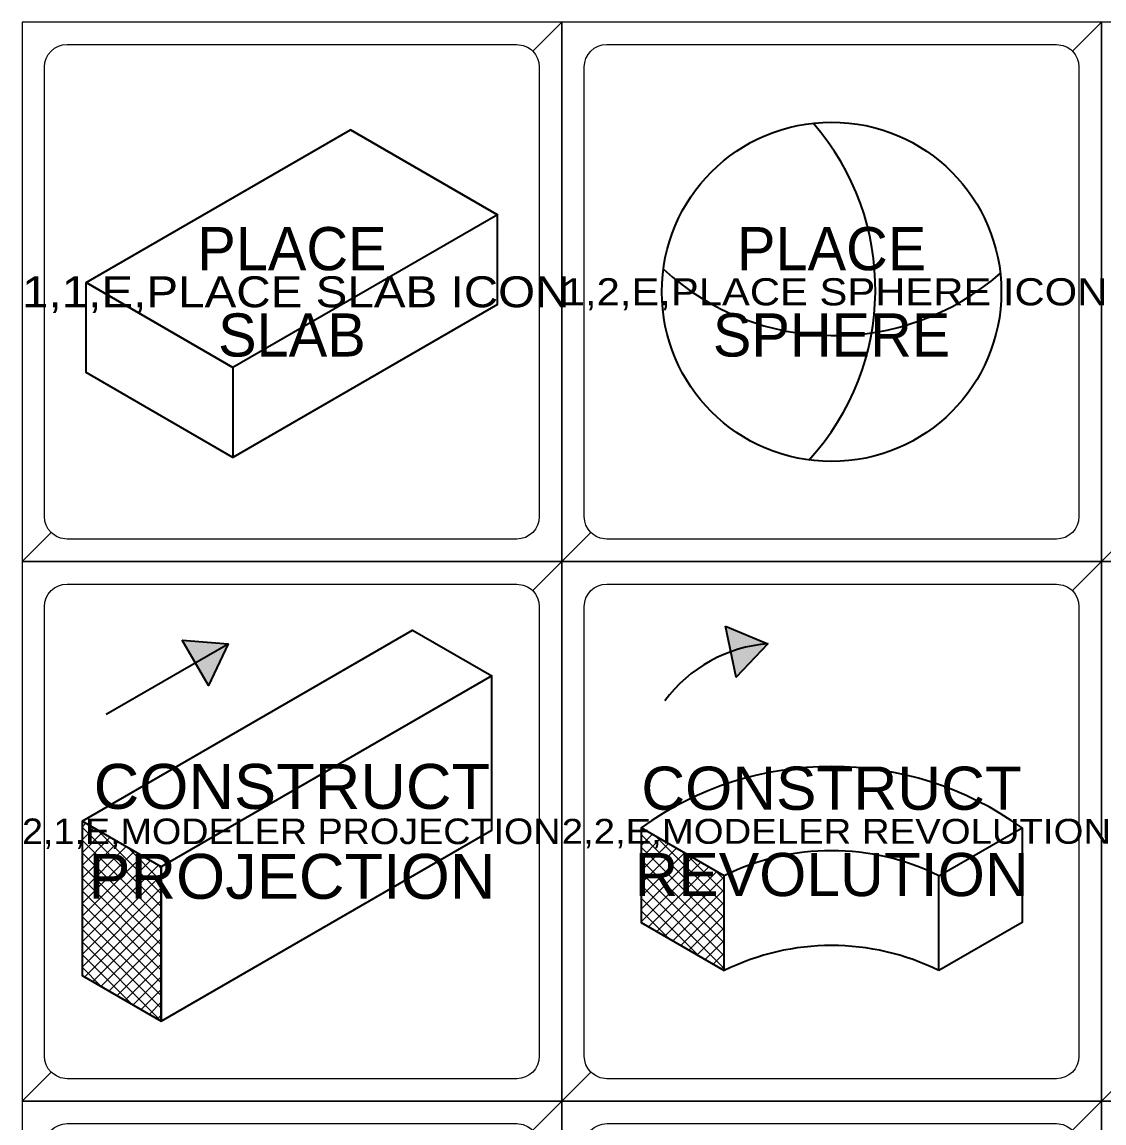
# Model space of a CAD drawing. Extents: x 95909.2 to 95923.3, y 90965 to 90971.2.
# Drawn here: x 95909.787 to 95910.99, y 90969.936 to 90971.16 of the extents above; entities that cross this region are included whole.
import ezdxf
from ezdxf.enums import TextEntityAlignment as Align

# ---------------------------------------------------------------- set-up
doc = ezdxf.new("R2010")
doc.units = 0
doc.header["$LTSCALE"] = 0.019
for name, color, linetype, lineweight in [('1', 7, 'Continuous', 25), ('10', 7, 'Continuous', 13), ('2', 7, 'Continuous', 25), ('3', 7, 'Continuous', 25), ('4', 7, 'Continuous', 25), ('6', 7, 'Continuous', 13)]:
    doc.layers.add(name, color=color, linetype=linetype, lineweight=lineweight)
doc.layers.add('5', color=7, linetype='Continuous')
doc.layers.add('63', color=7, linetype='Continuous')

msp = doc.modelspace()

# ---------------------------------------------------------------- hatches: boundary and pattern name
at = {"layer": '6'}
for points in [[(95910.5687, 90970.4886), (95910.6161, 90970.469), (95910.5807, 90970.4316)], [(95909.9649, 90970.473), (95910.0161, 90970.469), (95909.9941, 90970.4226)]]:
    msp.add_hatch(color=256, dxfattribs=at).paths.add_polyline_path(points)

# ---------------------------------------------------------------- linework, layer by layer
at = {"layer": '1'}
for points in [[(95909.7868, 90970.5603), (95910.3868, 90970.5603), (95910.3868, 90971.1603), (95909.7868, 90971.1603)], [(95910.3868, 90970.5603), (95910.9868, 90970.5603), (95910.9868, 90971.1603), (95910.3868, 90971.1603)], [(95910.9868, 90970.5603), (95911.5868, 90970.5603), (95911.5868, 90971.1603), (95910.9868, 90971.1603)], [(95909.7868, 90969.9603), (95910.3868, 90969.9603), (95910.3868, 90970.5603), (95909.7868, 90970.5603)], [(95910.3868, 90969.9603), (95910.9868, 90969.9603), (95910.9868, 90970.5603), (95910.3868, 90970.5603)], [(95910.9868, 90969.9603), (95911.5868, 90969.9603), (95911.5868, 90970.5603), (95910.9868, 90970.5603)], [(95909.7868, 90969.3603), (95910.3868, 90969.3603), (95910.3868, 90969.9603), (95909.7868, 90969.9603)], [(95910.3868, 90969.3603), (95910.9868, 90969.3603), (95910.9868, 90969.9603), (95910.3868, 90969.9603)], [(95910.9868, 90969.3603), (95911.5868, 90969.3603), (95911.5868, 90969.9603), (95910.9868, 90969.9603)]]:
    msp.add_lwpolyline(points, close=True, dxfattribs=at)
at = {"layer": '10'}
msp.add_lwpolyline([(95909.7868, 90971.1603), (95915.7868, 90971.1603), (95915.7868, 90966.3603), (95909.7868, 90966.3603)], close=True, dxfattribs=at)
at = {"layer": '2'}
for points in [[(95909.7868, 90970.5603), (95910.3868, 90970.5603), (95910.3868, 90971.1603), (95909.7868, 90971.1603)], [(95910.3868, 90970.5603), (95910.9868, 90970.5603), (95910.9868, 90971.1603), (95910.3868, 90971.1603)], [(95910.9868, 90970.5603), (95911.5868, 90970.5603), (95911.5868, 90971.1603), (95910.9868, 90971.1603)], [(95909.7868, 90969.9603), (95910.3868, 90969.9603), (95910.3868, 90970.5603), (95909.7868, 90970.5603)], [(95910.3868, 90969.9603), (95910.9868, 90969.9603), (95910.9868, 90970.5603), (95910.3868, 90970.5603)], [(95910.9868, 90969.9603), (95911.5868, 90969.9603), (95911.5868, 90970.5603), (95910.9868, 90970.5603)], [(95909.7868, 90969.3603), (95910.3868, 90969.3603), (95910.3868, 90969.9603), (95909.7868, 90969.9603)], [(95910.3868, 90969.3603), (95910.9868, 90969.3603), (95910.9868, 90969.9603), (95910.3868, 90969.9603)], [(95910.9868, 90969.3603), (95911.5868, 90969.3603), (95911.5868, 90969.9603), (95910.9868, 90969.9603)]]:
    msp.add_lwpolyline(points, close=True, dxfattribs=at)
at = {"layer": '3'}
for points in [[(95910.3868, 90971.1603), (95909.7868, 90971.1603), (95909.7868, 90970.5603), (95909.8191, 90970.5926), (95909.816, 90970.5964), (95909.8137, 90970.6007), (95909.8123, 90970.6054), (95909.8118, 90970.6103), (95909.8118, 90971.1103), (95909.8123, 90971.1152), (95909.8137, 90971.1199), (95909.816, 90971.1242), (95909.8191, 90971.128), (95909.8191, 90971.128), (95909.8229, 90971.1311), (95909.8272, 90971.1334), (95909.8319, 90971.1348), (95909.8368, 90971.1353), (95910.3368, 90971.1353), (95910.3441, 90971.1342), (95910.3486, 90971.1323), (95910.3527, 90971.1296), (95910.3545, 90971.128)], [(95910.9868, 90971.1603), (95910.3868, 90971.1603), (95910.3868, 90970.5603), (95910.4191, 90970.5926), (95910.416, 90970.5964), (95910.4137, 90970.6007), (95910.4123, 90970.6054), (95910.4118, 90970.6103), (95910.4118, 90971.1103), (95910.4123, 90971.1152), (95910.4137, 90971.1199), (95910.416, 90971.1242), (95910.4191, 90971.128), (95910.4191, 90971.128), (95910.4229, 90971.1311), (95910.4272, 90971.1334), (95910.4319, 90971.1348), (95910.4368, 90971.1353), (95910.9368, 90971.1353), (95910.9441, 90971.1342), (95910.9486, 90971.1323), (95910.9527, 90971.1296), (95910.9545, 90971.128)], [(95911.5868, 90971.1603), (95910.9868, 90971.1603), (95910.9868, 90970.5603), (95911.0191, 90970.5926), (95911.016, 90970.5964), (95911.0137, 90970.6007), (95911.0123, 90970.6054), (95911.0118, 90970.6103), (95911.0118, 90971.1103), (95911.0123, 90971.1152), (95911.0137, 90971.1199), (95911.016, 90971.1242), (95911.0191, 90971.128), (95911.0191, 90971.128), (95911.0229, 90971.1311), (95911.0272, 90971.1334), (95911.0319, 90971.1348), (95911.0368, 90971.1353), (95911.5368, 90971.1353), (95911.5441, 90971.1342), (95911.5486, 90971.1323), (95911.5527, 90971.1296), (95911.5545, 90971.128)], [(95910.3868, 90970.5603), (95909.7868, 90970.5603), (95909.7868, 90969.9603), (95909.8191, 90969.9926), (95909.816, 90969.9964), (95909.8137, 90970.0007), (95909.8123, 90970.0054), (95909.8118, 90970.0103), (95909.8118, 90970.5103), (95909.8123, 90970.5152), (95909.8137, 90970.5199), (95909.816, 90970.5242), (95909.8191, 90970.528), (95909.8191, 90970.528), (95909.8229, 90970.5311), (95909.8272, 90970.5334), (95909.8319, 90970.5348), (95909.8368, 90970.5353), (95910.3368, 90970.5353), (95910.3441, 90970.5342), (95910.3486, 90970.5323), (95910.3527, 90970.5296), (95910.3545, 90970.528)], [(95910.9868, 90970.5603), (95910.3868, 90970.5603), (95910.3868, 90969.9603), (95910.4191, 90969.9926), (95910.416, 90969.9964), (95910.4137, 90970.0007), (95910.4123, 90970.0054), (95910.4118, 90970.0103), (95910.4118, 90970.5103), (95910.4123, 90970.5152), (95910.4137, 90970.5199), (95910.416, 90970.5242), (95910.4191, 90970.528), (95910.4191, 90970.528), (95910.4229, 90970.5311), (95910.4272, 90970.5334), (95910.4319, 90970.5348), (95910.4368, 90970.5353), (95910.9368, 90970.5353), (95910.9441, 90970.5342), (95910.9486, 90970.5323), (95910.9527, 90970.5296), (95910.9545, 90970.528)], [(95911.5868, 90970.5603), (95910.9868, 90970.5603), (95910.9868, 90969.9603), (95911.0191, 90969.9926), (95911.016, 90969.9964), (95911.0137, 90970.0007), (95911.0123, 90970.0054), (95911.0118, 90970.0103), (95911.0118, 90970.5103), (95911.0123, 90970.5152), (95911.0137, 90970.5199), (95911.016, 90970.5242), (95911.0191, 90970.528), (95911.0191, 90970.528), (95911.0229, 90970.5311), (95911.0272, 90970.5334), (95911.0319, 90970.5348), (95911.0368, 90970.5353), (95911.5368, 90970.5353), (95911.5441, 90970.5342), (95911.5486, 90970.5323), (95911.5527, 90970.5296), (95911.5545, 90970.528)], [(95910.3868, 90969.9603), (95909.7868, 90969.9603), (95909.7868, 90969.3603), (95909.8191, 90969.3926), (95909.816, 90969.3964), (95909.8137, 90969.4007), (95909.8123, 90969.4054), (95909.8118, 90969.4103), (95909.8118, 90969.9103), (95909.8123, 90969.9152), (95909.8137, 90969.9199), (95909.816, 90969.9242), (95909.8191, 90969.928), (95909.8191, 90969.928), (95909.8229, 90969.9311), (95909.8272, 90969.9334), (95909.8319, 90969.9348), (95909.8368, 90969.9353), (95910.3368, 90969.9353), (95910.3441, 90969.9342), (95910.3486, 90969.9323), (95910.3527, 90969.9296), (95910.3545, 90969.928)], [(95910.9868, 90969.9603), (95910.3868, 90969.9603), (95910.3868, 90969.3603), (95910.4191, 90969.3926), (95910.416, 90969.3964), (95910.4137, 90969.4007), (95910.4123, 90969.4054), (95910.4118, 90969.4103), (95910.4118, 90969.9103), (95910.4123, 90969.9152), (95910.4137, 90969.9199), (95910.416, 90969.9242), (95910.4191, 90969.928), (95910.4191, 90969.928), (95910.4229, 90969.9311), (95910.4272, 90969.9334), (95910.4319, 90969.9348), (95910.4368, 90969.9353), (95910.9368, 90969.9353), (95910.9441, 90969.9342), (95910.9486, 90969.9323), (95910.9527, 90969.9296), (95910.9545, 90969.928)], [(95911.5868, 90969.9603), (95910.9868, 90969.9603), (95910.9868, 90969.3603), (95911.0191, 90969.3926), (95911.016, 90969.3964), (95911.0137, 90969.4007), (95911.0123, 90969.4054), (95911.0118, 90969.4103), (95911.0118, 90969.9103), (95911.0123, 90969.9152), (95911.0137, 90969.9199), (95911.016, 90969.9242), (95911.0191, 90969.928), (95911.0191, 90969.928), (95911.0229, 90969.9311), (95911.0272, 90969.9334), (95911.0319, 90969.9348), (95911.0368, 90969.9353), (95911.5368, 90969.9353), (95911.5441, 90969.9342), (95911.5486, 90969.9323), (95911.5527, 90969.9296), (95911.5545, 90969.928)]]:
    msp.add_lwpolyline(points, close=True, dxfattribs=at)
at = {"layer": '4'}
for points in [[(95909.7868, 90970.5603), (95910.3868, 90970.5603), (95910.3868, 90971.1603), (95910.3545, 90971.128), (95910.3576, 90971.1242), (95910.3599, 90971.1199), (95910.3613, 90971.1152), (95910.3618, 90971.1103), (95910.3618, 90970.6103), (95910.3613, 90970.6054), (95910.3599, 90970.6007), (95910.3576, 90970.5964), (95910.3545, 90970.5926), (95910.3545, 90970.5926), (95910.3507, 90970.5895), (95910.3464, 90970.5872), (95910.3417, 90970.5858), (95910.3368, 90970.5853), (95909.8368, 90970.5853), (95909.8295, 90970.5864), (95909.825, 90970.5883), (95909.8209, 90970.591), (95909.8191, 90970.5926)], [(95910.3868, 90970.5603), (95910.9868, 90970.5603), (95910.9868, 90971.1603), (95910.9545, 90971.128), (95910.9576, 90971.1242), (95910.9599, 90971.1199), (95910.9613, 90971.1152), (95910.9618, 90971.1103), (95910.9618, 90970.6103), (95910.9613, 90970.6054), (95910.9599, 90970.6007), (95910.9576, 90970.5964), (95910.9545, 90970.5926), (95910.9545, 90970.5926), (95910.9507, 90970.5895), (95910.9464, 90970.5872), (95910.9417, 90970.5858), (95910.9368, 90970.5853), (95910.4368, 90970.5853), (95910.4295, 90970.5864), (95910.425, 90970.5883), (95910.4209, 90970.591), (95910.4191, 90970.5926)], [(95910.9868, 90970.5603), (95911.5868, 90970.5603), (95911.5868, 90971.1603), (95911.5545, 90971.128), (95911.5576, 90971.1242), (95911.5599, 90971.1199), (95911.5613, 90971.1152), (95911.5618, 90971.1103), (95911.5618, 90970.6103), (95911.5613, 90970.6054), (95911.5599, 90970.6007), (95911.5576, 90970.5964), (95911.5545, 90970.5926), (95911.5545, 90970.5926), (95911.5507, 90970.5895), (95911.5464, 90970.5872), (95911.5417, 90970.5858), (95911.5368, 90970.5853), (95911.0368, 90970.5853), (95911.0295, 90970.5864), (95911.025, 90970.5883), (95911.0209, 90970.591), (95911.0191, 90970.5926)], [(95909.7868, 90969.9603), (95910.3868, 90969.9603), (95910.3868, 90970.5603), (95910.3545, 90970.528), (95910.3576, 90970.5242), (95910.3599, 90970.5199), (95910.3613, 90970.5152), (95910.3618, 90970.5103), (95910.3618, 90970.0103), (95910.3613, 90970.0054), (95910.3599, 90970.0007), (95910.3576, 90969.9964), (95910.3545, 90969.9926), (95910.3545, 90969.9926), (95910.3507, 90969.9895), (95910.3464, 90969.9872), (95910.3417, 90969.9858), (95910.3368, 90969.9853), (95909.8368, 90969.9853), (95909.8295, 90969.9864), (95909.825, 90969.9883), (95909.8209, 90969.991), (95909.8191, 90969.9926)], [(95910.3868, 90969.9603), (95910.9868, 90969.9603), (95910.9868, 90970.5603), (95910.9545, 90970.528), (95910.9576, 90970.5242), (95910.9599, 90970.5199), (95910.9613, 90970.5152), (95910.9618, 90970.5103), (95910.9618, 90970.0103), (95910.9613, 90970.0054), (95910.9599, 90970.0007), (95910.9576, 90969.9964), (95910.9545, 90969.9926), (95910.9545, 90969.9926), (95910.9507, 90969.9895), (95910.9464, 90969.9872), (95910.9417, 90969.9858), (95910.9368, 90969.9853), (95910.4368, 90969.9853), (95910.4295, 90969.9864), (95910.425, 90969.9883), (95910.4209, 90969.991), (95910.4191, 90969.9926)], [(95910.9868, 90969.9603), (95911.5868, 90969.9603), (95911.5868, 90970.5603), (95911.5545, 90970.528), (95911.5576, 90970.5242), (95911.5599, 90970.5199), (95911.5613, 90970.5152), (95911.5618, 90970.5103), (95911.5618, 90970.0103), (95911.5613, 90970.0054), (95911.5599, 90970.0007), (95911.5576, 90969.9964), (95911.5545, 90969.9926), (95911.5545, 90969.9926), (95911.5507, 90969.9895), (95911.5464, 90969.9872), (95911.5417, 90969.9858), (95911.5368, 90969.9853), (95911.0368, 90969.9853), (95911.0295, 90969.9864), (95911.025, 90969.9883), (95911.0209, 90969.991), (95911.0191, 90969.9926)], [(95909.7868, 90969.3603), (95910.3868, 90969.3603), (95910.3868, 90969.9603), (95910.3545, 90969.928), (95910.3576, 90969.9242), (95910.3599, 90969.9199), (95910.3613, 90969.9152), (95910.3618, 90969.9103), (95910.3618, 90969.4103), (95910.3613, 90969.4054), (95910.3599, 90969.4007), (95910.3576, 90969.3964), (95910.3545, 90969.3926), (95910.3545, 90969.3926), (95910.3507, 90969.3895), (95910.3464, 90969.3872), (95910.3417, 90969.3858), (95910.3368, 90969.3853), (95909.8368, 90969.3853), (95909.8295, 90969.3864), (95909.825, 90969.3883), (95909.8209, 90969.391), (95909.8191, 90969.3926)], [(95910.3868, 90969.3603), (95910.9868, 90969.3603), (95910.9868, 90969.9603), (95910.9545, 90969.928), (95910.9576, 90969.9242), (95910.9599, 90969.9199), (95910.9613, 90969.9152), (95910.9618, 90969.9103), (95910.9618, 90969.4103), (95910.9613, 90969.4054), (95910.9599, 90969.4007), (95910.9576, 90969.3964), (95910.9545, 90969.3926), (95910.9545, 90969.3926), (95910.9507, 90969.3895), (95910.9464, 90969.3872), (95910.9417, 90969.3858), (95910.9368, 90969.3853), (95910.4368, 90969.3853), (95910.4295, 90969.3864), (95910.425, 90969.3883), (95910.4209, 90969.391), (95910.4191, 90969.3926)]]:
    msp.add_lwpolyline(points, close=True, dxfattribs=at)
at = {"layer": '6', "lineweight": 35}
msp.add_line((95909.8804, 90970.3906), (95910.0161, 90970.469), dxfattribs=at)
at = {"layer": '6'}
for p, q in [((95909.8535, 90970.2649), (95909.8579, 90970.2693)), ((95909.8535, 90970.2648), (95909.9416, 90970.1767)), ((95909.8535, 90970.2508), (95909.8668, 90970.2641)), ((95909.8704, 90970.262), (95909.9416, 90970.1908)), ((95910.475, 90970.2587), (95910.4785, 90970.2622)), ((95909.8535, 90970.2366), (95909.8758, 90970.2589)), ((95909.8535, 90970.2225), (95909.8848, 90970.2537)), ((95909.8535, 90970.2507), (95909.9416, 90970.1626)), ((95910.475, 90970.2446), (95910.4874, 90970.257)), ((95910.475, 90970.2569), (95910.5674, 90970.1645)), ((95910.475, 90970.2304), (95910.4964, 90970.2519)), ((95910.4911, 90970.255), (95910.5674, 90970.1786)), ((95909.8535, 90970.2083), (95909.8937, 90970.2486)), ((95909.8535, 90970.1942), (95909.9027, 90970.2434)), ((95909.8535, 90970.18), (95909.9117, 90970.2382)), ((95909.8535, 90970.2365), (95909.9416, 90970.1484)), ((95909.9039, 90970.2427), (95909.9416, 90970.205)), ((95910.475, 90970.2163), (95910.5054, 90970.2467)), ((95910.475, 90970.2427), (95910.5674, 90970.1503)), ((95910.475, 90970.2022), (95910.5144, 90970.2415)), ((95910.475, 90970.188), (95910.5233, 90970.2364)), ((95909.8535, 90970.1659), (95909.9206, 90970.233)), ((95909.8535, 90970.1518), (95909.9296, 90970.2278)), ((95910.475, 90970.1739), (95910.5323, 90970.2312)), ((95910.475, 90970.2286), (95910.5674, 90970.1362)), ((95910.475, 90970.1597), (95910.5413, 90970.226)), ((95910.5244, 90970.2358), (95910.5674, 90970.1928)), ((95909.8535, 90970.1376), (95909.9385, 90970.2227)), ((95909.8535, 90970.2224), (95909.9416, 90970.1343)), ((95909.9374, 90970.2233), (95909.9416, 90970.2191)), ((95910.475, 90970.2144), (95910.5674, 90970.122)), ((95910.4834, 90970.154), (95910.5503, 90970.2209)), ((95910.4924, 90970.1488), (95910.5592, 90970.2157)), ((95910.5577, 90970.2166), (95910.5674, 90970.2069)), ((95909.8535, 90970.1235), (95909.9416, 90970.2116)), ((95909.8535, 90970.2082), (95909.9416, 90970.1201)), ((95910.475, 90970.2003), (95910.5674, 90970.1079)), ((95910.5014, 90970.1437), (95910.5674, 90970.2097)), ((95909.8535, 90970.1093), (95909.9416, 90970.1974)), ((95909.8535, 90970.1941), (95909.9416, 90970.106)), ((95910.5103, 90970.1385), (95910.5674, 90970.1956)), ((95909.8535, 90970.18), (95909.9416, 90970.0919)), ((95909.8567, 90970.0984), (95909.9416, 90970.1833)), ((95910.475, 90970.1862), (95910.5396, 90970.1216)), ((95910.5193, 90970.1333), (95910.5674, 90970.1814)), ((95909.8535, 90970.1658), (95909.9416, 90970.0777)), ((95909.8656, 90970.0932), (95909.9416, 90970.1692)), ((95910.475, 90970.172), (95910.5061, 90970.1409)), ((95910.5282, 90970.1281), (95910.5674, 90970.1673)), ((95909.8535, 90970.1517), (95909.9416, 90970.0636)), ((95909.8746, 90970.088), (95909.9416, 90970.155)), ((95910.5372, 90970.1229), (95910.5674, 90970.1531)), ((95909.8836, 90970.0828), (95909.9416, 90970.1409)), ((95910.5462, 90970.1178), (95910.5674, 90970.139)), ((95909.8535, 90970.1375), (95909.9416, 90970.0494)), ((95909.8925, 90970.0777), (95909.9416, 90970.1267)), ((95909.8535, 90970.1234), (95909.9084, 90970.0685)), ((95910.5551, 90970.1126), (95910.5674, 90970.1249)), ((95909.8535, 90970.1092), (95909.8749, 90970.0878)), ((95909.9015, 90970.0725), (95909.9416, 90970.1126)), ((95910.5641, 90970.1074), (95910.5674, 90970.1107)), ((95909.9105, 90970.0673), (95909.9416, 90970.0984)), ((95909.9194, 90970.0621), (95909.9416, 90970.0843)), ((95909.9284, 90970.0569), (95909.9416, 90970.0702)), ((95909.9373, 90970.0518), (95909.9416, 90970.056))]:
    msp.add_line(p, q, dxfattribs=at)
at = {"layer": '6', "lineweight": 35}
for points in [[(95909.8581, 90970.8705), (95910.1521, 90971.0403), (95910.3153, 90970.946), (95910.0213, 90970.7763)], [(95910.0213, 90970.7763), (95910.0213, 90970.6762), (95909.8581, 90970.7704), (95909.8581, 90970.8705)], [(95909.8535, 90970.2718), (95910.221, 90970.484), (95910.3091, 90970.4331), (95909.9416, 90970.2209)], [(95910.5687, 90970.4886), (95910.6161, 90970.469), (95910.5807, 90970.4316)], [(95909.9649, 90970.473), (95910.0161, 90970.469), (95909.9941, 90970.4226)], [(95909.9416, 90970.2209), (95909.9416, 90970.0493), (95910.3091, 90970.2615), (95910.3091, 90970.4331)], [(95909.8535, 90970.2718), (95909.8535, 90970.1002), (95909.9416, 90970.0493), (95909.9416, 90970.2209)], [(95910.5674, 90970.1055), (95910.5674, 90970.211), (95910.475, 90970.2642), (95910.475, 90970.1589)], [(95910.8061, 90970.1055), (95910.8061, 90970.211), (95910.8985, 90970.2642), (95910.8985, 90970.1589)]]:
    msp.add_lwpolyline(points, close=True, dxfattribs=at)
for points in [[(95910.3153, 90970.846), (95910.3153, 90970.946), (95910.1521, 90971.0403)], [(95910.3153, 90970.846), (95910.0213, 90970.6762), (95909.8581, 90970.7704)]]:
    msp.add_lwpolyline(points, dxfattribs=at)
msp.add_circle((95910.68676, 90970.86026), 0.1887, dxfattribs=at)
for centre, radius, start, end in [((95910.45481, 90970.86317), 0.28068, 317.42058, 41.14029), ((95910.68967, 90971.09221), 0.28068, 227.42058, 311.14029), ((95910.62798, 90970.31231), 0.15709, 94.32654, 143.6635), ((95910.68676, 90969.96893), 0.36342, 54.3618, 125.6382), ((95910.68676, 90969.96969), 0.26913, 63.68023, 116.31977), ((95910.68676, 90969.86425), 0.26913, 63.68023, 116.31977)]:
    msp.add_arc(centre, radius, start, end, dxfattribs=at)

# ---------------------------------------------------------------- texts
at = {"layer": '5'}
for s, p in [('PLACE', (95910.08685, 90970.8843)), ('PLACE', (95910.68685, 90970.8843)), ('SLAB', (95910.08685, 90970.7883)), ('SPHERE', (95910.6868, 90970.7883))]:
    msp.add_text(s, height=0.048, dxfattribs=at).set_placement(p, align=Align.CENTER)
at = {"layer": '5', "width": 1.05}
for s, height, p in [('CONSTRUCT', 0.05, (95910.0868, 90970.2853)), ('CONSTRUCT', 0.048, (95910.6868, 90970.2843)), ('REVOLUTION', 0.048, (95910.6868, 90970.1883)), ('PROJECTION', 0.05, (95910.08675, 90970.1853))]:
    msp.add_text(s, height=height, dxfattribs=at).set_placement(p, align=Align.CENTER)
at = {"layer": '63'}
for s, height, width, p in [('1,1,E,PLACE SLAB ICON', 0.0344, 1.15, (95909.7868, 90970.8431)), ('1,2,E,PLACE SPHERE ICON', 0.0302, 1.15, (95910.3868, 90970.8452)), ('2,1,E,MODELER PROJECTION', 0.0285, 1.1, (95909.7868, 90970.2461)), ('2,2,E,MODELER REVOLUTION', 0.0277, 1.15, (95910.3868, 90970.2465))]:
    msp.add_text(s, height=height, dxfattribs=dict(at, width=width)).set_placement(p)

doc.saveas('drawing.dxf')
